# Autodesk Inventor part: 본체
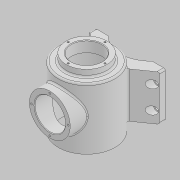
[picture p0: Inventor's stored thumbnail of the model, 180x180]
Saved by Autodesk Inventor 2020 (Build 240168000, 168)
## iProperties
Created: 2023-12
Part Number: 본체
Material: 일반
Document SubType Name: Modeling
Designer: 1강의실14
Density: 1 g/cm^3
Appearance: 기본값
Mass: 459.082 g
Surface Area: 1029.55 cm^2
Volume: 459.082 cm^3
Author: 1강의실14
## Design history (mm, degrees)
sketch "스케치1"
  geometry: L1 (-62, -77)-(-38.5, -77); L2 (-62, -77)-(-62, -67); L3 (-62, -67)-(-26.694, -42.278); L4 (38.5, -77)-(62, -77); L5 (62, -77)-(62, -67); L6 (62, -67)-(26.694, -42.278); A1 r 50 centre (0, 0) between (-26.694, -42.278) and (26.694, -42.278); A2 r 52.096 centre (0, -112.096) between (0, -60) and (-38.5, -77); A3 r 52.096 centre (0, -112.096) between (38.5, -77) and (0, -60); 1 further point
  constraints: 12 end point, 6 point on circle, 3 centre point, 1 coincident, 1 concentric, 1 horizontal, 1 perpendicular, 1 vertical, 1 vertical alignment
  dimensions: "d0" = 23.5 distance of L1.end L1.start; "d1" = 10 distance of L1.start L2.end; "d2" = 55 deg angle of L3 L2; "d5" = 100 diameter of A1; "d9" = 23.5 distance of L4.start L4.end; "d10" = 10 distance of L4.end L5.end; "d11" = 55 deg angle of L5 L6; "d16" = 38.5 horizontal distance of L4.start A2.start; "d17" = 17 distance from line of L1 A2.start; "d18" = 110 deg angle of L3 L6; "d19" = 62 distance from line of A3.centre L5; "d20" = 77 distance from line of L1 point (0, 0); "d21" = 52.09559 radius of A2; "d22" = 72.50188 distance from line of A3.centre L6
extrude "돌출2" new body sketch "스케치1" distance "d25" = 80; taper "d26" = 0 deg
feature "본체 이동1"
extrude "돌출3" join sketch "스케치1" distance "d30" = 108; taper "d31" = 0 deg
sketch "스케치2"
  geometry: C1 r 36 at (0, 0); 1 further point
  constraints: 1 centre point, 1 coincident
  dimensions: "d32" = 72 diameter of C1
extrude "돌출4" join sketch "스케치2" distance "d33" = 12; taper "d34" = 0 deg
sketch "스케치3"
  geometry: 2 further points
  constraints: 1 coincident
hole "구멍1" sketch "스케치3" at (0, 0) diameter "d35" = 54; stored, may be unused: countersink angle "d39" = 90 deg, drill point angle "d41" = 0 deg; dims "d36" = 8, "d37" = 54, "d38" = 4, "d40" = 19
sketch "스케치4"
  geometry: 2 further points
  constraints: 1 coincident
node "작업 평면2"
sketch "스케치7"
  geometry: C1 r 36 at (0, -50); 1 further point
  constraints: 1 centre point, 1 vertical alignment
  dimensions: "d43" = 72 diameter of C1; "d44" = 50 distance of C1.centre point (0, 0)
extrude "돌출5" join sketch "스케치7" stored distance "d45" = 12; taper "d46" = 0 deg
sketch "스케치9"
  geometry: C1 r 27 at (0, 0) reference; 5 further points
  constraints: 2 vertical alignment, 1 horizontal alignment
  dimensions: "d54" = 65 distance of point (32.5, 0) point (-32.5, 0); "d55" = 65 distance of point (0, 32.5) point (0, -32.5); "d56" = 32.5 distance of C1.centre point (0, 32.5); "d57" = 32.5 distance of point (32.5, 0) C1.centre; "d58" = 32.5 distance of point (-32.5, 0) C1.centre
node "작업 평면3"
sketch "스케치13"
  geometry: L1 (-38.5, -20)-(-62, -20) reference; L2 (62, -20)-(38.5, -20) reference; L3 (38.5, -100)-(62, -100) reference; L4 (-62, -20)-(-62, -100) reference; 5 further points
  constraints: 1 vertical alignment
  dimensions: "d72" = 20 distance from line of point (-54, -40) L1; "d73" = 108 distance of point (54, -40) point (-54, -40); "d74" = 20 distance from line of point (54, -40) L2; "d75" = 40 distance of point (54, -80) point (54, -40); "d76" = 20 distance from line of L3 point (54, -80); "d77" = 40 distance of point (-54, -80) point (-54, -40); "d78" = 8 distance from line of L4 point (-54, -40)
hole "구멍3" sketch "스케치13" at (54, -40), (-54, -40), (-54, -80), (54, -80) diameter "d79" = 9; stored, may be unused: countersink angle "d83" = 90 deg, drill point angle "d85" = 0 deg; dims "d80" = 8, "d81" = 54, "d82" = 4, "d84" = 6
sketch "스케치14"
  geometry: C1 r 4.5 at (108, 0) reference; C2 r 4.5 at (108, -40) reference; C3 r 4.5 at (0, -40) reference; C4 r 4.5 at (108, 0) reference; C5 r 4.5 at (0, -40) reference; 5 further points
  constraints: 3 coincident
hole "구멍4" sketch "스케치14" diameter "d86" = 14; stored, may be unused: countersink angle "d90" = 90 deg, drill point angle "d92" = 0 deg; dims "d87" = 8, "d88" = 54, "d89" = 4, "d91" = 6
hole "구멍5" sketch "스케치14" diameter "d93" = 14; stored, may be unused: countersink angle "d97" = 90 deg, drill point angle "d99" = 0 deg; dims "d94" = 8, "d95" = 54, "d96" = 4, "d98" = 6
hole "구멍6" sketch "스케치14" diameter "d100" = 14; stored, may be unused: countersink angle "d104" = 90 deg, drill point angle "d106" = 0 deg; dims "d101" = 8, "d102" = 54, "d103" = 4, "d105" = 6
hole "구멍7" sketch "스케치14" diameter "d107" = 14; stored, may be unused: countersink angle "d111" = 90 deg, drill point angle "d113" = 0 deg; dims "d108" = 8, "d109" = 54, "d110" = 4, "d112" = 6
fillet "모깎기1" dims "d114" = 3
fillet "모깎기2" dims "d115" = 3
fillet "모깎기3" dims "d116" = 3
sketch "스케치15"
  geometry: 2 further points
hole "구멍8" sketch "스케치15" at (0, 0) diameter "d117" = 54; stored, may be unused: countersink angle "d121" = 90 deg, drill point angle "d123" = 0 deg; dims "d118" = 8, "d119" = 54, "d120" = 4, "d122" = 85
sketch "스케치16"
  geometry: C1 r 27 at (0, 0) reference; 4 further points
  constraints: 2 horizontal alignment, 2 vertical alignment
  dimensions: "d124" = 65 distance of point (-32.5, 0) point (32.5, 0); "d125" = 65 distance of point (0, 32.5) point (0, -32.5); "d126" = 32.5 distance of C1.centre point (32.5, 0); "d127" = 32.5 distance of C1.centre point (0, -32.5)
hole "구멍9" sketch "스케치16" at (32.5, 0), (0, 32.5), (-32.5, 0), (0, -32.5) diameter "d128" = 3.242; stored, may be unused: countersink angle "d132" = 90 deg, drill point angle "d134" = 118 deg; dims "d129" = 8, "d130" = 54, "d131" = 4, "d133" = 10
sketch "스케치17"
  geometry: C1 r 27 at (0, 0) reference; 5 further points
  constraints: 2 horizontal alignment, 2 vertical alignment
  dimensions: "d135" = 65 distance of point (-32.5, 0) point (32.5, 0); "d136" = 65 distance of point (0, 32.5) point (0, -32.5); "d137" = 32.5 distance of point (0, 0) point (32.5, 0); "d138" = 32.5 distance of point (0, 0) point (0, -32.5)
hole "구멍10" sketch "스케치17" at (32.5, 0), (0, 32.5), (-32.5, 0), (0, -32.5) diameter "d139" = 3.242; stored, may be unused: countersink angle "d143" = 90 deg, drill point angle "d145" = 118 deg; dims "d140" = 8, "d141" = 54, "d142" = 4, "d144" = 10
node "작업 평면4"
node "작업 평면5"
sketch "스케치20"
  geometry: 2 further points
  constraints: 1 other
  dimensions: "d147" = 50 horizontal distance of point (0, 0) point (-50, 0.457)
feature "엠보싱1" sketch "스케치20" dims "d148" = 0.5, "d149" = 0
hole "구멍11" sketch "스케치4" diameter "d150" = 86; stored, may be unused: countersink angle "d154" = 90 deg, drill point angle "d156" = 0 deg; dims "d151" = 8, "d152" = 54, "d153" = 2, "d155" = 10
fillet "모깎기4" dims "d157" = 3
fillet "모깎기5" dims "d158" = 3
chamfer "모따기1" distance "d159" = 1; stored, may be unused: second distance "d160" = 2, angle "d161" = 45 deg
chamfer "모따기2" distance "d162" = 1; stored, may be unused: second distance "d163" = 2, angle "d164" = 45 deg
node "솔리드2"
feature "A9D066F2-1C7D-4E18-AEED-F7BC21143FA4" dims "d35" = 54, "d36" = 8, "d37" = 54, "d38" = 4, "d39" = 90 deg, "d40" = 19, "d41" = 0
other parameters: "d27" = 0, "d29" = 0, "d42" = 65, "d71" = -77, "d146" = -55
